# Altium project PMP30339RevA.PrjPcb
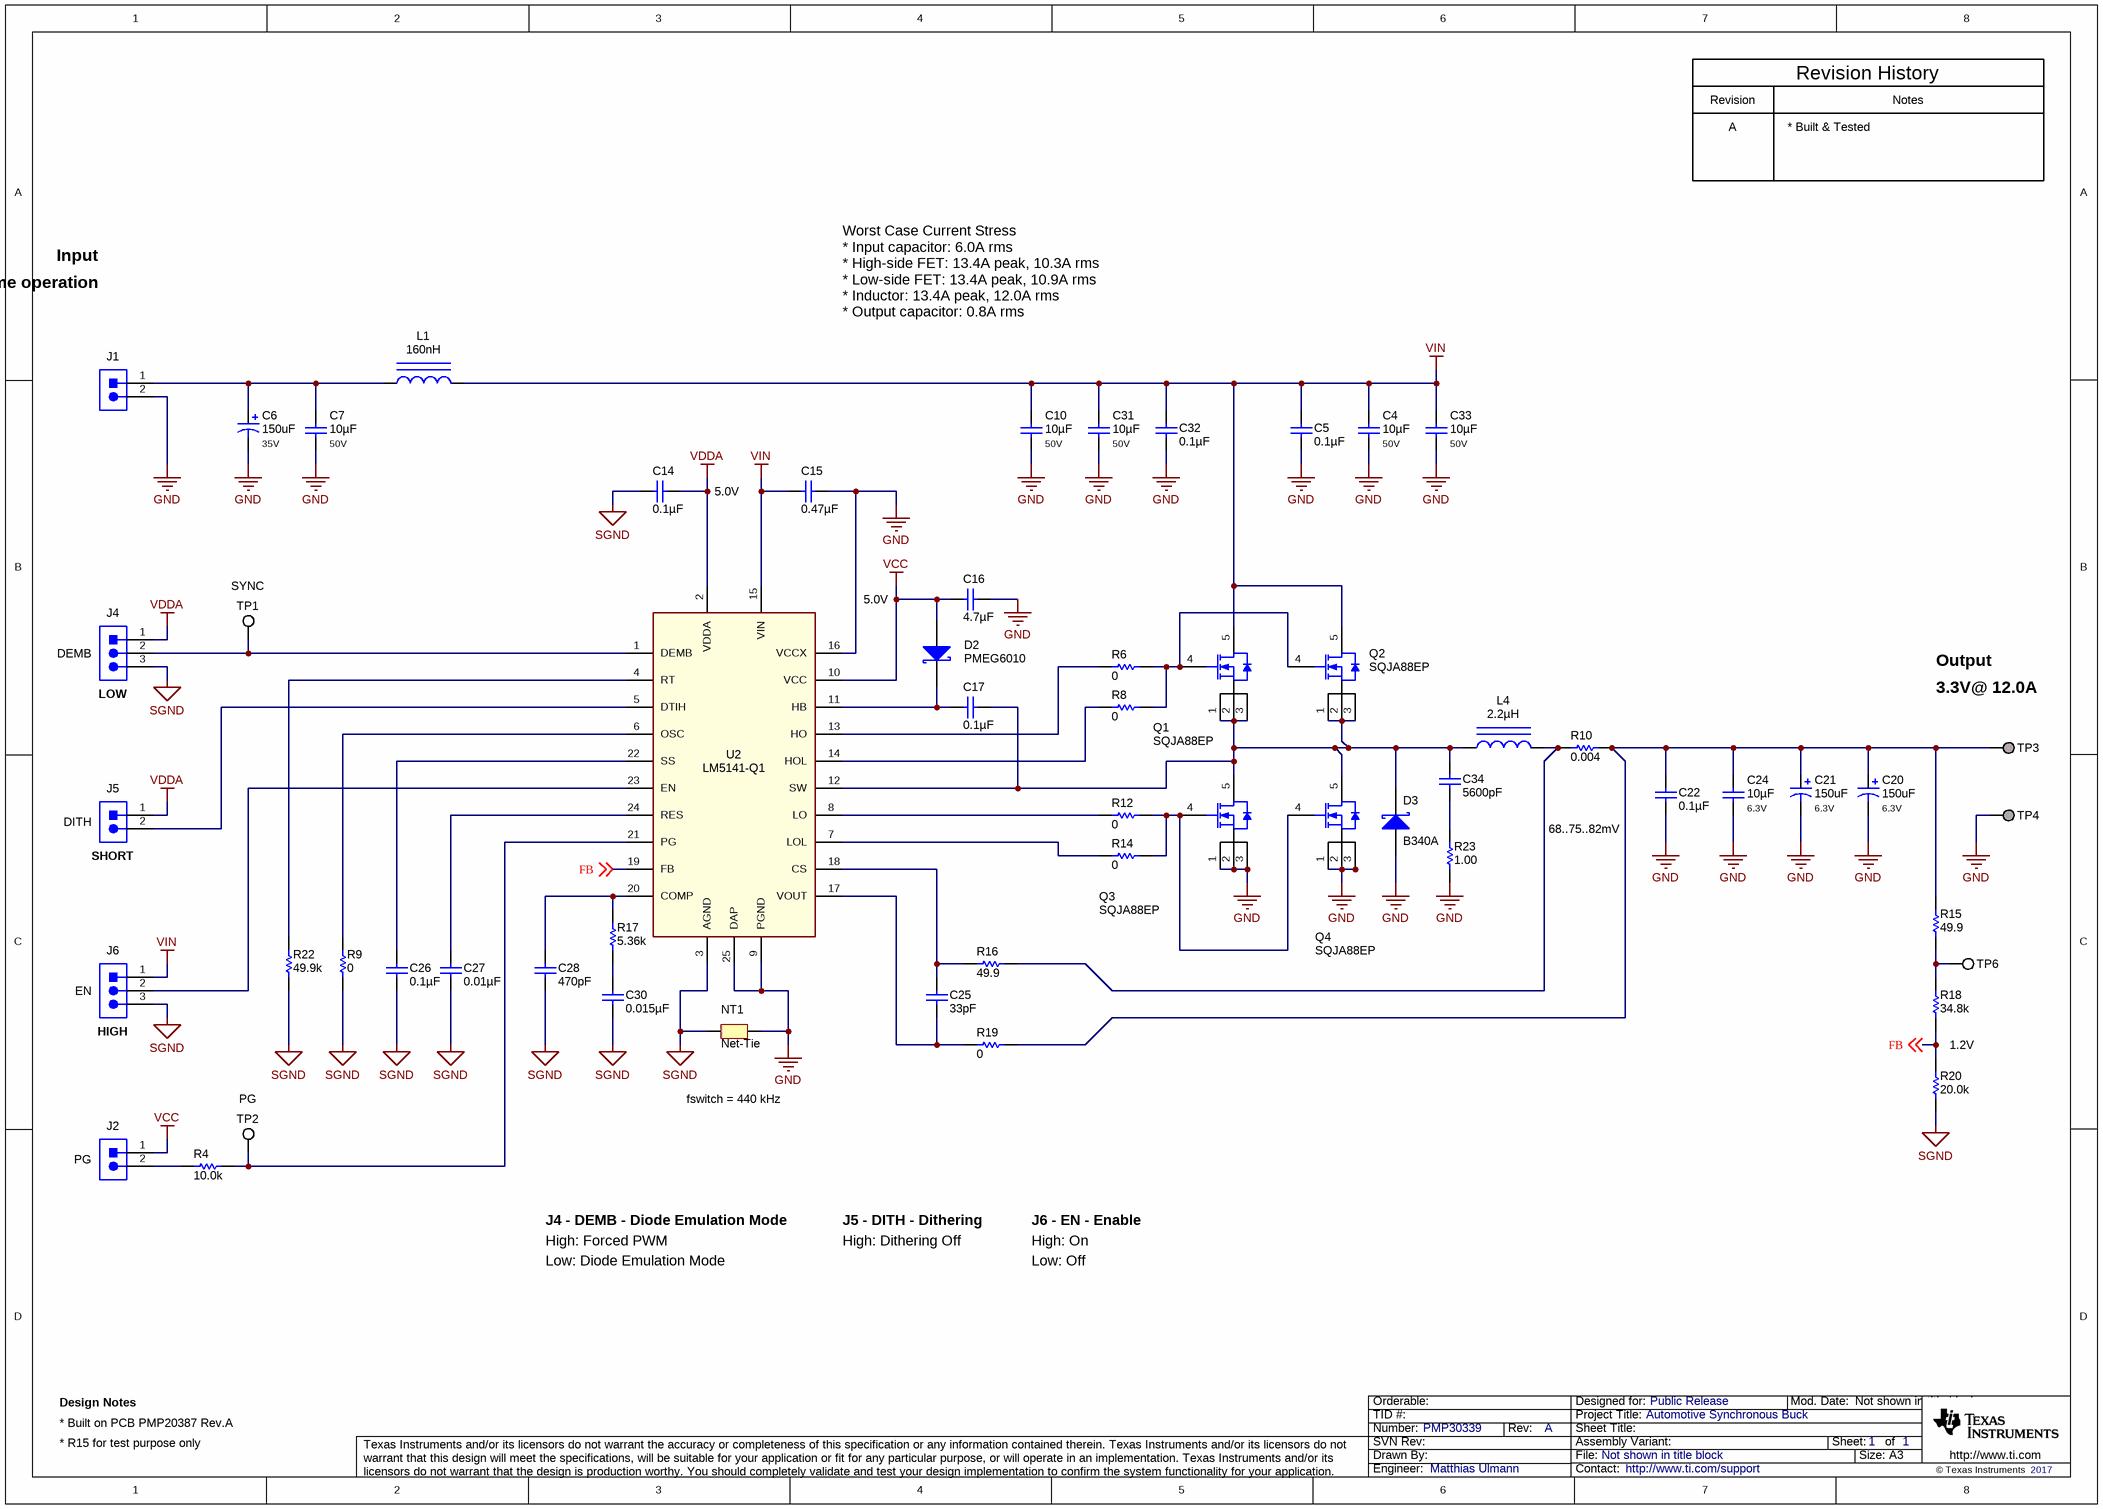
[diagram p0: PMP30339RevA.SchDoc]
TechSupport: http://www.ti.com/support; SCH_Rev: A; PRJ_Title: Automotive Synchronous Buck; PRJ_Number: PMP30339; PRJ_Engineer: Matthias Ulmann; PRJ_Customer: Public Release; PCB_Rev: A; PCB_Layout: M. Ulmann; CopyrightYear: 2017
1 sheet, 57 parts. Net scope: global (net labels, ports and power ports of the same name join across sheets).
Board file: PMP30339RevA.PcbDoc

## Sheet PMP30339RevA.SchDoc
size A3; Date: Not shown in title block; ApprovedBy: Not shown in title block; CheckedBy: Not shown in title block; Author: Not shown in title block; CompanyName: Not shown in title block; Engineer: Not shown in title block; Organization: Not shown in title block; Address1: Not shown in title block; Address2: Not shown in title block; Address3: Not shown in title block; Address4: Not shown in title block; DocumentNumber: 1; Revision: Use project parameter SCH_Rev; SheetNumber: 1; SheetTotal: 1; PageSetup: Record=PageOptions¦CenterHorizontal=True¦CenterVertical=True¦PrintScale=0.68¦XCorrection=1.00¦YCorrection=1.00¦PrintKind=0¦BorderSize=5000000¦LeftOffset=0¦BottomOffset=0¦Orientation=2¦PaperLength=1000¦PaperWidth=1000¦Scale=100¦PaperSource=15¦PrintQuality=600¦MediaType=1¦DitherType=10¦PrintScaleMode=1¦PaperKind=A4¦PaperIndex=9

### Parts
C4  ValueDisplayed: 10µF  Value2: 50V  [1210_270]  (hidden comment: GRM32ER71H106KA12L)
C5  ValueDisplayed: 0.1µF  [0603]  (hidden comment: GRM188R71H104KA93D)
C6  VDC_V: 35V  ValueDisplayed: 150uF  [SM_RADIAL_8MM]  (hidden comment: EEHZC1V151P)
C7  ValueDisplayed: 10µF  Value2: 50V  [1210_270]  (hidden comment: GRM32ER71H106KA12L)
C10  ValueDisplayed: 10µF  Value2: 50V  [1210_270]  (hidden comment: GRM32ER71H106KA12L)
C14  ValueDisplayed: 0.1µF  [0603]  (hidden comment: GRM188R71H104KA93D)
C15  ValueDisplayed: 0.47µF  [0805L]  (hidden comment: GRM21BR72A474KA73L)
C16  ValueDisplayed: 4.7µF  [0603]  (hidden comment: GRM188R61C475KAAJ)
C17  ValueDisplayed: 0.1µF  [0603]  (hidden comment: GRM188R71H104KA93D)
C20  VDC_V: 6.3V  ValueDisplayed: 150uF  [CAPSMT_62_E61]  (hidden comment: 6SVPE150M)
C21  VDC_V: 6.3V  ValueDisplayed: 150uF  [CAPSMT_62_E61]  (hidden comment: 6SVPE150M)
C22  ValueDisplayed: 0.1µF  [0603]  (hidden comment: GRM188R71H104KA93D)
C24  ValueDisplayed: 10µF  Value2: 6.3V  [1206_180]  (hidden comment: GRM31CR70J106KA01L)
C25  ValueDisplayed: 33pF  [0603]  (hidden comment: 06035A330JAT2A)
C26  ValueDisplayed: 0.1µF  [0603]  (hidden comment: GRM188R71H104KA93D)
C27  ValueDisplayed: 0.01µF  [0603]  (hidden comment: C1608X7R2A103M)
C28  ValueDisplayed: 470pF  [0603]  (hidden comment: GRM188R71H471KA01D)
C30  ValueDisplayed: 0.015µF  [0603]  (hidden comment: GRM188R71H153KA01D)
C31  ValueDisplayed: 10µF  Value2: 50V  [1210_270]  (hidden comment: GRM32ER71H106KA12L)
C32  ValueDisplayed: 0.1µF  [0603]  (hidden comment: GRM188R71H104KA93D)
C33  ValueDisplayed: 10µF  Value2: 50V  [1210_270]  (hidden comment: GRM32ER71H106KA12L)
C34  ValueDisplayed: 5600pF  [0603]  (hidden comment: GRM188R71H562KA01D)
D2  PMEG6010  [SOD-323F]
D3  B340A  [SMA]
J1  1729018  [Phoenix_1729018]  (value not drawn)
J2  61300211121  [WURTH_61300211121]  (value not drawn)
J4  61300311121  [WURTH_61300311121]  (value not drawn)
J5  61300211121  [WURTH_61300211121]  (value not drawn)
J6  61300311121  [WURTH_61300311121]  (value not drawn)
L1  ValueDisplayed: 160nH  [XAL7070]  (hidden comment: XAL7070-161MEB)
L4  ValueDisplayed: 2.2µH  [XAL1010]  (hidden comment: XAL1010-222MEB)
NT1  Net-Tie  [Net-Tie_10mil]  (net tie, no BOM)
Q1  SQJA88EP  [PowerPAK_SO-8L]
Q2  SQJA88EP  [PowerPAK_SO-8L]
Q3  SQJA88EP  [PowerPAK_SO-8L]
Q4  SQJA88EP  [PowerPAK_SO-8L]
R4  ValueDisplayed: 10.0k  [0603]  (hidden comment: CRCW060310K0FKEA)
R6  ValueDisplayed: 0  [0603]  (hidden comment: CRCW06030000Z0EA)
R8  ValueDisplayed: 0  [0603]  (hidden comment: CRCW06030000Z0EA)
R9  ValueDisplayed: 0  [0603]  (hidden comment: CRCW06030000Z0EA)
R10  ValueDisplayed: 0.004  [2512]  (hidden comment: ERJ-M1WSF4M0U)
R12  ValueDisplayed: 0  [0603]  (hidden comment: CRCW06030000Z0EA)
R14  ValueDisplayed: 0  [0603]  (hidden comment: CRCW06030000Z0EA)
R15  ValueDisplayed: 49.9  [0603]  (hidden comment: CRCW060349R9FKEA)
R16  ValueDisplayed: 49.9  [0603]  (hidden comment: CRCW060349R9FKEA)
R17  ValueDisplayed: 5.36k  [0603]  (hidden comment: CRCW06035K36FKEA)
R18  ValueDisplayed: 34.8k  [0603]  (hidden comment: CRCW060334K8FKEA)
R19  ValueDisplayed: 0  [0603]  (hidden comment: CRCW06030000Z0EA)
R20  ValueDisplayed: 20.0k  [0603]  (hidden comment: CRCW060320K0FKEA)
R22  ValueDisplayed: 49.9k  [0603]  (hidden comment: CRCW060349K9FKEA)
R23  ValueDisplayed: 1.00  [1206]  (hidden comment: CRCW12061R00FKEA)
TP1  5002  [Keystone5002]  (value not drawn)
TP2  5002  [Keystone5002]  (value not drawn)
TP3  Suggest using a net name here  [Keystone1598-2]  (value not drawn)
TP4  Suggest using a net name here  [Keystone1598-2]  (value not drawn)
TP6  Bode_A  [Keystone5012]  (value not drawn)
U2  LM5141-Q1  [RGE0024H]

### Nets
GND: C4.2 C5.1 C6.2(-) C7.2 C10.2 C15.2 C16.1 C20.2(-) C21.2(-) C22.2 C24.2 C31.2 C32.1 C33.2 D3.2(A) J1.2 NT1.2 Q3.1(S) Q3.2(S) Q3.3(S) Q4.1(S) Q4.2(S) Q4.3(S) R23.1 TP4.1 U2.9(PGND) U2.16(VCCX) U2.25(DAP)
SGND: C14.1 C26.1 C27.2 C28.2 C30.2 J4.3 J6.3 NT1.1 R9.2 R20.1 R22.1 U2.3(AGND)
VCC: C16.2 D2.2(A) J2.1 U2.10(VCC)
VDDA: C14.2 J4.1 J5.1 U2.2(VDDA)
VIN: C4.1 C5.2 C10.1 C15.1 C31.1 C32.2 C33.1 J6.1 L1.2 Q1.5(D) Q2.5(D) U2.15(VIN)
FB: R18.1 R20.2 U2.19(FB) ; off-sheet FB
NetC6_1: C6.1(+) C7.1 J1.1 L1.1
NetC17_1: C17.1 D2.1(K) U2.11(HB)
NetC17_2: C17.2 C34.1 D3.1(K) L4.1 Q1.1(S) Q1.2(S) Q1.3(S) Q2.1(S) Q2.2(S) Q2.3(S) Q3.5(D) Q4.5(D) U2.12(SW)
NetC20_1: C20.1(+) C21.1(+) C22.1 C24.1 R10.2 R15.2 R19.2 TP3.1
NetC25_1: C25.1 R19.1 U2.17(VOUT)
NetC25_2: C25.2 R16.1 U2.18(CS)
NetC26_2: C26.2 U2.22(SS)
NetC27_1: C27.1 U2.24(RES)
NetC28_1: C28.1 R17.2 U2.20(COMP)
NetC30_1: C30.1 R17.1
NetC34_2: C34.2 R23.2
NetJ2_2: J2.2 R4.1
NetJ4_2: J4.2 TP1.1 U2.1(DEMB)
NetJ5_2: J5.2 U2.5(DTIH)
NetJ6_2: J6.2 U2.23(EN)
NetL4_2: L4.2 R10.1 R16.2
NetQ1_4: Q1.4(G) Q2.4(G) R6.2 R8.2
NetQ3_4: Q3.4(G) Q4.4(G) R12.2 R14.2
NetR4_2: R4.2 TP2.1 U2.21(PG)
NetR6_1: R6.1 U2.13(HO)
NetR8_1: R8.1 U2.14(HOL)
NetR9_1: R9.1 U2.6(OSC)
NetR12_1: R12.1 U2.8(LO)
NetR14_1: R14.1 U2.7(LOL)
NetR15_1: R15.1 R18.2 TP6.1
NetR22_2: R22.2 U2.4(RT)

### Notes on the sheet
- Revision
- Revision History
- Notes
- A
- * Built & Tested
- Input
- 9.0 .. 18.0V continuous / 4.5 .. 32V short time operation
- Worst Case Current Stress
  * Input capacitor: 6.0A rms
  * High-side FET: 13.4A peak, 10.3A rms
  * Low-side FET: 13.4A peak, 10.9A rms
  * Inductor: 13.4A peak, 12.0A rms
  * Output capacitor: 0.8A rms
- 5.0V
- (near TP1) SYNC
- (near J4) DEMB
- (near J4) LOW
- Output
- (near TP3) 3.3V@ 12.0A
- (near J5) DITH
- (near J5) SHORT
- 68..75..82mV
- (near J6) EN
- (near J6) HIGH
- 1.2V
- (near TP2) PG
- fswitch = 440 kHz
- (near J2) PG
- J4 - DEMB - Diode Emulation Mode
- High: Forced PWM
- Low: Diode Emulation Mode
- J5 - DITH - Dithering
- High: Dithering Off
- J6 - EN - Enable
- High: On
- Low: Off
- Design Notes
- * Built on PCB PMP20387 Rev.A
- * R15 for test purpose only

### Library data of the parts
C4 C7 C10 C31 C33 = GRM32ER71H106KA12L: CAP, CERM, 10 µF, 50 V,+/- 10%, X7R, 1210; Manufacturer: MuRata; Polarized: N; CompType: Capacitor; Value: 10uF; U/M: EA; Cap_F: 0.00001; Tolerance_%: 10; VDC_V: 50; TaMin_C: -55; TaMax_C: 125; Cap_Case: 1210; SizeArea_mm2: 8; SizeAreaWB_mm2: 14.7; SizeX_mm: 3.2; SizeY_mm: 2.5; SizeZ_mm: 2.7; AEC Category: Q200; Green_Lifecycle: Active; Green_REACh: Passed
C5 C14 C17 C22 C26 C32 = GRM188R71H104KA93D: CAP, CERM, 0.1 µF, 50 V, +/- 10%, X7R, 0603; Manufacturer: MuRata; Polarized: N; CompType: Capacitor; Value: 0.1uF; U/M: EA; Cap_F: 0.0000001; Tolerance_%: 10; Value1: Unknown; VDC_V: 50; Value2: 50V; TaMin_C: -55; TaMax_C: 125; SizeArea_mm2: 1.28; SizeAreaWB_mm2: 4.68; SizeX_mm: 1.6; SizeY_mm: 0.8; SizeZ_mm: 1; AEC Category: Q200
C6 = CMP-0012604-2: CAP, Polymer Hybrid, 150 uF, 35 V, +/- 20%, 27 ohm, 8x10 SMD; Manufacturer: Panasonic; TaMin_C: -55°C; ESR_ohm: 27; Polarized: Y; SizeAreaWB_mm2: 113.3; Value1: 27 ohm; U/M: EA; Value: 150uF; TaMax_C: 125°C; SizeZ_mm: 10.2; SizeX_mm: 9; SizeY_mm: 8.3; SizeArea_mm2: 74.7; CompType: Capacitor; Cap_F: 150µF; IRMS_A: 1.6A; AEC Category: Q200
C15 = GRM21BR72A474KA73L: CAP, CERM, 0.47 µF, 100 V, +/- 10%, X7R, 0805; Manufacturer: MuRata; Polarized: N; CompType: Capacitor; Value: 0.47uF; U/M: EA; Cap_F: 0.00000047; Tolerance_%: 10; Value1: Unknown; VDC_V: 100; Value2: 100V; TaMin_C: -55; TaMax_C: 125; Cap_Case: 0805
C16 = GRM188R61C475KAAJ: CAP, CERM, 4.7 µF, 16 V, +/- 10%, X5R, 0603; Manufacturer: MuRata; Polarized: N; CompType: Capacitor; Value: 4.7uF; U/M: EA; Cap_F: 0.0000047; Tolerance_%: 10; Value1: Unknown; VDC_V: 16; Value2: 16V; TaMin_C: -55; TaMax_C: 85
C20 C21 = CMP-0012159-2: CAP, Aluminum Polymer, 150 uF, 6.3 V, +/- 20%, 0.012 ohm, E61 SMD; Manufacturer: Panasonic; TaMin_C: -55°C; ESR_ohm: 0.012; Polarized: Y; SizeAreaWB_mm2: 53.29; U/M: EA; Value: 150uF; TaMax_C: 105°C; SizeZ_mm: 5.8; SizeX_mm: 5.3; SizeArea_mm2: 28.09; CompType: Capacitor; Cap_F: 150µF; IRMS_A: 3.52A; AEC Category: Q200
C24 = GRM31CR70J106KA01L: CAP, CERM, 10 µF, 6.3 V,+/- 10%, X7R, 1206; Manufacturer: MuRata; Polarized: N; CompType: Capacitor; Value: 10uF; U/M: EA; Cap_F: 0.00001; Tolerance_%: 10; VDC_V: 6.3; TaMin_C: -55; TaMax_C: 125; Cap_Case: 1206; SizeArea_mm2: 5.12; SizeAreaWB_mm2: 10.92; SizeX_mm: 3.2; SizeY_mm: 1.6; SizeZ_mm: 1.8; AEC Category: Q200
C25 = 06035A330JAT2A: CAP, CERM, 33 pF, 50 V, +/- 5%, C0G/NP0, 0603; Manufacturer: AVX; Polarized: N; CompType: Capacitor; Value: 33pF; U/M: EA; Cap_F: 0.000000000033; Tolerance_%: 5; ESR_ohm: 0.209; Value1: 0.209 ohm; VDC_V: 50; Value2: 50V; TaMin_C: -55; TaMax_C: 125
C27 = C1608X7R2A103M: CAP, CERM, 0.01 µF, 100 V, +/- 20%, X7R, 0603; Manufacturer: TDK; Polarized: N; CompType: Capacitor; Value: 0.01uF; U/M: EA; Cap_F: 0.00000001; Tolerance_%: 20; ESR_ohm: 0.0661; Value1: 0.0661 ohm; VDC_V: 100; Value2: 100V; TaMin_C: -55; TaMax_C: 125
C28 = GRM188R71H471KA01D: CAP, CERM, 470 pF, 50 V,+/- 10%, X7R, 0603; Manufacturer: MuRata; Polarized: N; CompType: Capacitor; Value: 470pF; U/M: EA; Cap_F: 0.00000000047; Tolerance_%: 10; VDC_V: 50; Value2: 50V; TaMin_C: -55; TaMax_C: 125; SizeArea_mm2: 1.28; SizeAreaWB_mm2: 4.68; SizeX_mm: 1.6; SizeY_mm: 0.8; SizeZ_mm: 1; AEC Category: Q200; Green_Lifecycle: Active; Green_REACh: Passed
C30 = GRM188R71H153KA01D: CAP, CERM, 0.015 µF, 50 V,+/- 10%, X7R, 0603; Manufacturer: MuRata; Polarized: N; CompType: Capacitor; Value: 0.015uF; U/M: EA; Cap_F: 0.000000015; Tolerance_%: 10; VDC_V: 50; Value2: 50V; TaMin_C: -55; TaMax_C: 125; SizeArea_mm2: 1.28; SizeAreaWB_mm2: 4.68; SizeX_mm: 1.6; SizeY_mm: 0.8; SizeZ_mm: 1; AEC Category: Q200; Green_Lifecycle: Active; Green_REACh: Passed
C34 = GRM188R71H562KA01D: CAP, CERM, 5600 pF, 50 V,+/- 10%, X7R, 0603; Manufacturer: MuRata; Polarized: N; CompType: Capacitor; Value: 5600pF; U/M: EA; Cap_F: 0.0000000056; Tolerance_%: 10; VDC_V: 50; Value2: 50V; TaMin_C: -55; TaMax_C: 125; SizeArea_mm2: 1.28; SizeAreaWB_mm2: 4.68; SizeX_mm: 1.6; SizeY_mm: 0.8; SizeZ_mm: 1; AEC Category: Q200; Green_Lifecycle: Active; Green_REACh: Passed
D2 = PMEG6010CEJ,115: Diode, Schottky, 60 V, 1 A, SOD-323F; Manufacturer: NXP Semiconductor; U/M: EA; Vf_V: 0.66; Value: 60V; Value1: 1A; Value2: 0.66V; Io_A: 1; Vr_V: 60; TJmax_C: 150
D3 = B340A-13-F: Diode, Schottky, 40 V, 3 A, SMA; Manufacturer: Diodes Inc.; U/M: EA; Vf_V: 0.5; Value: 40V; Value1: 3A; Value2: 0.5V; Io_A: 3; Vr_V: 40; TJmax_C: 125; RJC_CperW: 25; SizeAreaWB_mm2: 37.3428; SizeArea_mm2: 16.3228; SizeX_mm: 5.59; SizeY_mm: 2.92; SizeZ_mm: 2.87; AEC Category: Q101; Green_Lifecycle: Active; Green_REACh: Passed
J1 = 1729018: TERM BLOCK 2POS 5mm, TH; Manufacturer: Phoenix Contact; SymbolCreator: a0412235; CompType: Header; U/M: EA
J2 J5 = 61300211121: Header, 2.54 mm, 2x1, Gold, TH; Manufacturer: Wurth Elektronik; SymbolCreator: a0412235
J4 J6 = 61300311121: Header, 2.54 mm, 3x1, Gold, TH; Manufacturer: Wurth Elektronik; SymbolCreator: a0799628
L1 = XAL7070-161MEB: Inductor, Shielded, Composite, 160 nH, 36.1 A, 0.00075 ohm, SMD; Manufacturer: Coilcraft; Value: 160nH; Ind_H: 160.0E-9; Imax_A: 36.1; Irms: 36.1A @ 40C rise; Isat: 78A @ 30% inductance drop; Value2: 36.1A; SizeAreaWB_mm2: 87.4; SizeArea_mm2: 54; SizeX_mm: 7.2; SizeY_mm: 7.5; SizeZ_mm: 7; AEC Category: Q200; Green_Lifecycle: Not Set; Green_REACh: Incomplete
L4 = XAL1010-222MEB: Inductor, Shielded, Composite, 2.2 µH, 32 A, 0.00255 ohm, SMD; Manufacturer: Coilcraft; Value: 2.2uH; Ind_H: 2.2E-6; Imax_A: 32; Irms: 32A @ 40C rise; Isat: 34A @ 30% inductance drop; Value2: 32A; SizeAreaWB_mm2: 159.6; SizeArea_mm2: 113; SizeX_mm: 11.3; SizeY_mm: 10; AEC Category: Q200; Green_Lifecycle: Not Set; Green_REACh: Incomplete
NT1 = Net-Tie: Single point connection between nets.; SymbolCreator: codlsc
Q1-Q4 = SQJA60EP: MOSFET, N-CH, 40 V, 30 A, AEC-Q101, PowerPAK_SO-8L; Manufacturer: Vishay-Siliconix; Alternate Manufacturer: None; SymbolCreator: a0412235; U/M: EA; ChType: N; Value: 40V; VdsMax_V: 60; Rdson45_ohm: 0.0095; Value2: 21 nC; QgTyp_nC: 21; Vgs_V: 20; IdsMax_A: 30; SizeAreaWB_mm2: 58.1095; SizeArea_mm2: 31.5495; SizeX_mm: 6.15; SizeY_mm: 5.13; SizeZ_mm: 1.14; AEC Category: Q101; AEC Qualified: Y
R4 = CRCW060310K0FKEA: RES, 10.0 k, 1%, 0.1 W, 0603; Manufacturer: Vishay-Dale; CompType: Resistor; Value: 10.0k; Res_ohm: 10000; Value_Code: 10k0; Tolerance_%: 1; Power_W: 0.1; Value2: 0.1W; VDC_V: 75; TempCo: 100 ppm/C; EIA_Code: E96; U/M: EA
R6 R8 R12 R14 = CRCW06030000Z0EA: RES, 0, 5%, 0.1 W, 0603; Manufacturer: Vishay-Dale; CompType: Resistor; Value: 0; Value_Code: 0000; Tolerance_%: 5; Power_W: 0.1; Value2: 0.1W; VDC_V: 75; TempCo: 200 ppm/C; SizeArea_mm2: 1.28; SizeX_mm: 1.6; SizeY_mm: 0.8; SizeZ_mm: 1; EIA_Code: E24; U/M: EA; AEC Category: Q200
R9 R19 = CRCW06030000Z0EA: RES, 0, 5%, 0.1 W, 0603; Manufacturer: Vishay-Dale; CompType: Resistor; Value: 0; Value_Code: 0000; Tolerance_%: 5; Power_W: 0.1; Value2: 0.1W; VDC_V: 75; TempCo: 200 ppm/C; EIA_Code: E24; U/M: EA
R10 = ERJ-M1WSF4M0U: RES, 0.004, 1%, 1 W, 2512; Manufacturer: Panasonic; CompType: Resistor; Value: 0.004; Value_Code: 4L000; Tolerance_%: 1; Value2: 1W; TempCo: 350 ppm/C; SizeArea_mm2: 20.16; SizeX_mm: 6.3; SizeY_mm: 3.2; SizeZ_mm: 0.71; U/M: EA; AEC Category: Q200
R15 R16 = CRCW060349R9FKEA: RES, 49.9, 1%, 0.1 W, 0603; Manufacturer: Vishay-Dale; CompType: Resistor; Value: 49.9; Value_Code: 49R9; Tolerance_%: 1; Power_W: 0.1; Value2: 0.1W; VDC_V: 75; TempCo: 100 ppm/C; EIA_Code: E96; U/M: EA
R17 = CRCW06035K36FKEA: RES, 5.36 k, 1%, 0.1 W, 0603; Manufacturer: Vishay-Dale; CompType: Resistor; Value: 5.36k; Res_ohm: 5360; Value_Code: 5k36; Tolerance_%: 1; Power_W: 0.1; Value2: 0.1W; VDC_V: 75; TempCo: 100 ppm/C; SizeArea_mm2: 1.28; SizeX_mm: 1.6; SizeY_mm: 0.8; EIA_Code: E96; U/M: EA; AEC Category: Q200; Green_Lifecycle: Active; Green_REACh: Passed
R18 = CRCW060334K8FKEA: RES, 34.8 k, 1%, 0.1 W, 0603; Manufacturer: Vishay-Dale; CompType: Resistor; Value: 34.8k; Res_ohm: 34800; Value_Code: 34k8; Tolerance_%: 1; Power_W: 0.1; Value2: 0.1W; VDC_V: 75; TempCo: 100 ppm/C; SizeArea_mm2: 1.28; SizeX_mm: 1.6; SizeY_mm: 0.8; EIA_Code: E96; U/M: EA; AEC Category: Q200
R20 = CRCW060320K0FKEA: RES, 20.0 k, 1%, 0.1 W, 0603; Manufacturer: Vishay-Dale; CompType: Resistor; Value: 20.0k; Res_ohm: 20000; Value_Code: 20k0; Tolerance_%: 1; Power_W: 0.1; Value2: 0.1W; VDC_V: 75; TempCo: 100 ppm/C; EIA_Code: E96; U/M: EA
R22 = CRCW060349K9FKEA: RES, 49.9 k, 1%, 0.1 W, 0603; Manufacturer: Vishay-Dale; CompType: Resistor; Value: 49.9k; Res_ohm: 49900; Value_Code: 49k9; Tolerance_%: 1; Power_W: 0.1; Value2: 0.1W; VDC_V: 75; TempCo: 100 ppm/C; SizeArea_mm2: 1.28; SizeX_mm: 1.6; SizeY_mm: 0.8; EIA_Code: E96; U/M: EA; AEC Category: Q200; Green_Lifecycle: Active; Green_REACh: Passed
R23 = CRCW12061R00FKEA: RES, 1.00, 1%, 0.25 W, 1206; Manufacturer: Vishay-Dale; CompType: Resistor; Value: 1.00; Res_ohm: 1; Value_Code: 1R00; Power_W: 0.25; Value2: 0.25W; VDC_V: 200; TempCo: 100 ppm/C; SizeArea_mm2: 5.12; SizeX_mm: 3.2; SizeY_mm: 1.6; SizeZ_mm: 1.35; EIA_Code: E96; U/M: EA; AEC Category: Q200; Green_Lifecycle: Active; Green_REACh: Passed
TP1 TP2 = 5002: Test Point, Miniature, White, TH; Manufacturer: Keystone; CompType: Test Point Loop; U/M: EA
TP3 TP4 = 1598-2: Terminal, Turret, TH, Triple; Manufacturer: Keystone; CompType: Turret Terminal; U/M: EA
TP6 = 5012: Test Point, Multipurpose, White, TH; Manufacturer: Keystone; CompType: Test Point Loop; ContactFinish: Silver
U2 = LM5141QRGEQ1: IC, PWM, Buck Controller, w/ Dither; Manufacturer: Texas Instruments; SymbolVersion: use current date i.e. 2008-05-20; SymbolCreator: Use a-id; U/M: EA, IN, or GM

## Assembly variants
001: all parts fitted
